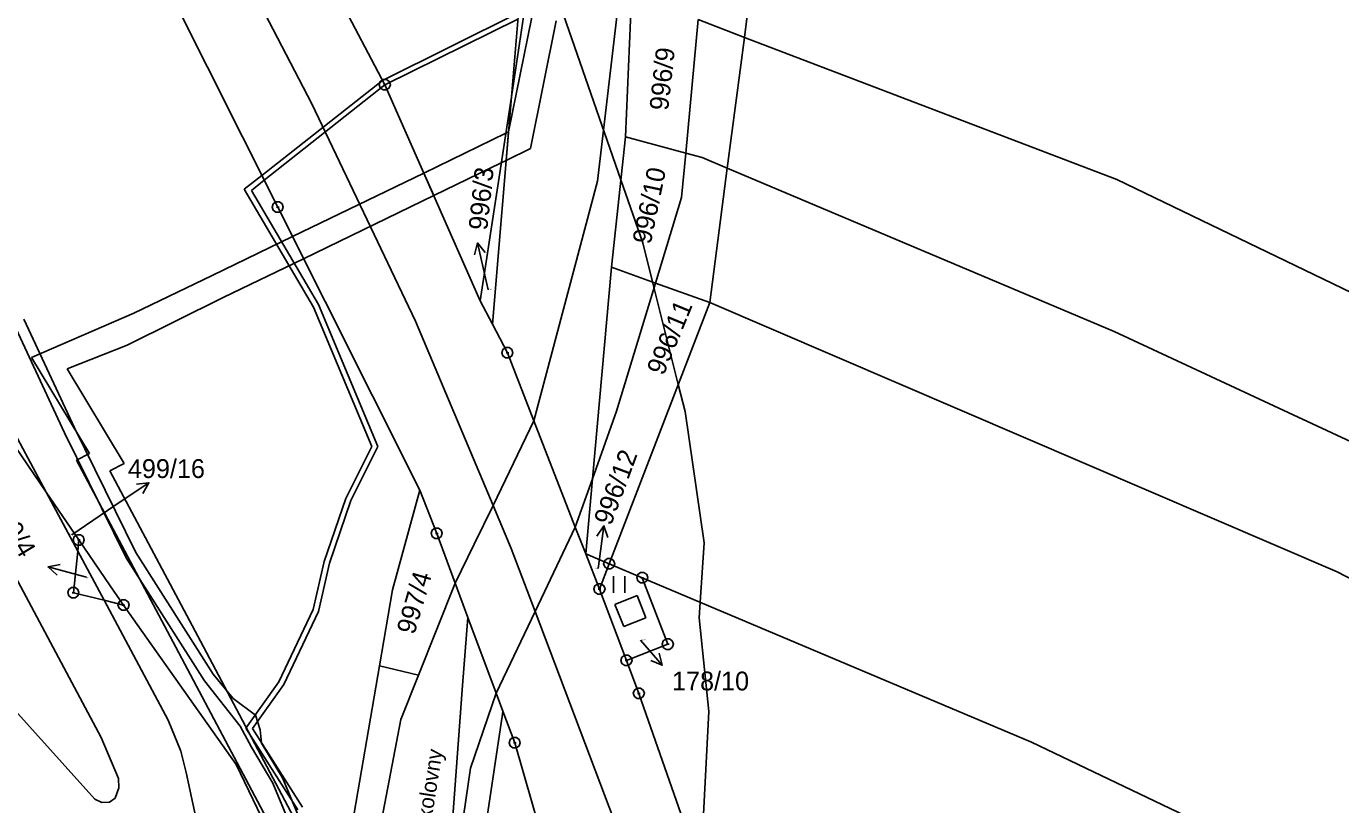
# Model space of a CAD drawing. Extents: x -755359 to -754474, y -1162585 to -1161655.
# Drawn here: x -755164.4 to -755045.7, y -1162431.7 to -1162361.4 of the extents above; entities that cross this region are included whole.
import ezdxf

# ---------------------------------------------------------------- set-up
doc = ezdxf.new("R2010")
doc.units = 0
for name, color, linetype in [('Vrstva 1', 7, 'Continuous'), ('Vrstva 11', 7, 'Continuous'), ('Vrstva 13', 7, 'Continuous'), ('Vrstva 2', 7, 'Continuous'), ('Vrstva 3', 7, 'Continuous'), ('Vrstva 4', 7, 'Continuous'), ('Vrstva 6', 7, 'Continuous'), ('Vrstva 7', 7, 'Continuous'), ('Vrstva 8', 7, 'Continuous')]:
    doc.layers.add(name, color=color, linetype=linetype)

msp = doc.modelspace()

# ---------------------------------------------------------------- linework, layer by layer
at = {"layer": 'Vrstva 1'}
for p, q in [((-755143.37, -1162345.14), (-755132.01, -1162366.71)), ((-755120.58, -1162367.79), (-755117.64, -1162348.46)), ((-755099.55, -1162362.44), (-755098.12, -1162351.47)), ((-755141.68, -1162377.77), (-755154.66, -1162351.82)), ((-755162.59, -1162403.5), (-755194.7, -1162356.4)), ((-755119.82, -1162358.61), (-755120.58, -1162367.79)), ((-755109.73, -1162358.47), (-755110.28, -1162371.41)), ((-755103.73, -1162360.81), (-755099.55, -1162362.44)), ((-755101.09, -1162374.25), (-755099.55, -1162362.44)), ((-755099.55, -1162362.44), (-755065.93, -1162375.26)), ((-755132.01, -1162366.71), (-755123.39, -1162386.22)), ((-755123.39, -1162386.22), (-755120.58, -1162367.79)), ((-755120.58, -1162367.79), (-755122.29, -1162388.33)), ((-755111.53, -1162383.2), (-755110.28, -1162371.41)), ((-755110.28, -1162371.41), (-755104.84, -1162372.89)), ((-755104.84, -1162372.89), (-755103.37, -1162373.29)), ((-755103.37, -1162373.29), (-755101.09, -1162374.25)), ((-755102.66, -1162386.37), (-755101.09, -1162374.25)), ((-755101.09, -1162374.25), (-755066.17, -1162388.99)), ((-755065.93, -1162375.26), (-755012.09, -1162401.26)), ((-755128.84, -1162403.34), (-755141.68, -1162377.77)), ((-755111.53, -1162383.2), (-755113.26, -1162402.31)), ((-755107.56, -1162384.62), (-755111.53, -1162383.2)), ((-755102.66, -1162386.37), (-755107.56, -1162384.62)), ((-755178.91, -1162385.78), (-755157.62, -1162425.68)), ((-755122.29, -1162388.33), (-755123.39, -1162386.22)), ((-755111.75, -1162409.98), (-755102.66, -1162386.37)), ((-755046.04, -1162410.7), (-755102.66, -1162386.37)), ((-755120.94, -1162390.93), (-755122.29, -1162388.33)), ((-755066.17, -1162388.99), (-755029.41, -1162406.11)), ((-755118.55, -1162397.08), (-755120.94, -1162390.93)), ((-755158.19, -1162431.25), (-755190.23, -1162395.62)), ((-755114.81, -1162406.67), (-755118.55, -1162397.08)), ((-755113.26, -1162402.31), (-755113.87, -1162409.08)), ((-755162.59, -1162403.5), (-755159.74, -1162408.83)), ((-755159.64, -1162407.83), (-755162.59, -1162403.5)), ((-755131.31, -1162412.32), (-755128.84, -1162403.34)), ((-755127.32, -1162407.23), (-755128.84, -1162403.34)), ((-755125.65, -1162411.73), (-755127.32, -1162407.23)), ((-755113.87, -1162409.08), (-755114.81, -1162406.67)), ((-755159.64, -1162407.83), (-755159.74, -1162408.83)), ((-755159.64, -1162407.83), (-755156.82, -1162411.96)), ((-755159.74, -1162408.83), (-755160.13, -1162412.59)), ((-755113.87, -1162409.08), (-755111.75, -1162409.98)), ((-755112.63, -1162412.26), (-755113.87, -1162409.08)), ((-755112.63, -1162412.26), (-755111.75, -1162409.98)), ((-755111.75, -1162409.98), (-755108.76, -1162411.24)), ((-754989.82, -1162440.1), (-755046.04, -1162410.7)), ((-755155.59, -1162413.71), (-755156.82, -1162411.96)), ((-755125.65, -1162411.73), (-755128.96, -1162420.05)), ((-755124.5, -1162414.82), (-755125.65, -1162411.73)), ((-755108.76, -1162411.24), (-755073.63, -1162426.1)), ((-755106.46, -1162417.25), (-755108.76, -1162411.24)), ((-755160.13, -1162412.59), (-755157.36, -1162413.27)), ((-755157.36, -1162413.27), (-755151.56, -1162424.12)), ((-755157.36, -1162413.27), (-755155.59, -1162413.71)), ((-755132.49, -1162419.21), (-755131.31, -1162412.32)), ((-755112.63, -1162412.26), (-755110.19, -1162418.72)), ((-755145.43, -1162428.12), (-755155.59, -1162413.71)), ((-755124.5, -1162414.82), (-755125.01, -1162420.99)), ((-755121.95, -1162421.66), (-755124.5, -1162414.82)), ((-755110.19, -1162418.72), (-755106.46, -1162417.25)), ((-755137.03, -1162445.6), (-755132.49, -1162419.21)), ((-755128.96, -1162420.05), (-755132.49, -1162419.21)), ((-755110.19, -1162418.72), (-755109.07, -1162421.69)), ((-755125.01, -1162420.99), (-755126.31, -1162438.59)), ((-755121.35, -1162423.28), (-755121.95, -1162421.66)), ((-755102.04, -1162441.81), (-755109.07, -1162421.69)), ((-755121.39, -1162423.55), (-755122.9, -1162433.61)), ((-755121.35, -1162423.28), (-755121.39, -1162423.55)), ((-755120.28, -1162426.16), (-755121.35, -1162423.28)), ((-755151.56, -1162424.12), (-755150.43, -1162426.9)), ((-755157.62, -1162425.68), (-755156.05, -1162429.38)), ((-755117.59, -1162435.42), (-755120.28, -1162426.16)), ((-755047.73, -1162438.47), (-755073.63, -1162426.1)), ((-755150.43, -1162426.9), (-755149.93, -1162428.84)), ((-755149.93, -1162428.84), (-755146.21, -1162446.45)), ((-755137.03, -1162445.6), (-755145.43, -1162428.12)), ((-755156.05, -1162429.38), (-755156.03, -1162430.21)), ((-755156.34, -1162431.15), (-755156.88, -1162431.52)), ((-755156.03, -1162430.21), (-755156.34, -1162431.15)), ((-755157.56, -1162431.53), (-755158.19, -1162431.25)), ((-755156.88, -1162431.52), (-755157.56, -1162431.53))]:
    msp.add_line(p, q, dxfattribs=at)
at = {"layer": 'Vrstva 11'}
for p, q in [((-755116.36, -1162358.98), (-755110.69, -1162375.3)), ((-755110.69, -1162375.3), (-755108.72, -1162380.99)), ((-755108.72, -1162380.99), (-755107.83, -1162384.52)), ((-755107.83, -1162384.52), (-755105.51, -1162393.77)), ((-755105.51, -1162393.77), (-755104.89, -1162396.23)), ((-755104.89, -1162396.23), (-755103.19, -1162408.08)), ((-755103.19, -1162408.08), (-755103.53, -1162413.45)), ((-755103.53, -1162413.45), (-755103.62, -1162414.85)), ((-755103.62, -1162414.85), (-755102.77, -1162423.32)), ((-755102.77, -1162423.32), (-755103.29, -1162433.76))]:
    msp.add_line(p, q, dxfattribs=at)
at = {"layer": 'Vrstva 13'}
for p, q in [((-755132.22, -1162366.32), (-755119.95, -1162360.2)), ((-755120, -1162360.79), (-755132.01, -1162366.71)), ((-755120.84, -1162370.97), (-755118.74, -1162360.6)), ((-755116.54, -1162360.94), (-755118.85, -1162372.47)), ((-755143.12, -1162374.89), (-755132.22, -1162366.32)), ((-755132.01, -1162366.71), (-755142.9, -1162375.34)), ((-755132.01, -1162366.71), (-755132.22, -1162366.32)), ((-755132.22, -1162366.32), (-755132.01, -1162366.71)), ((-755128.49, -1162374.68), (-755121.08, -1162371.08)), ((-755121.08, -1162371.08), (-755120.84, -1162370.97)), ((-755120.84, -1162370.97), (-755121.06, -1162373.54)), ((-755121.06, -1162373.54), (-755120.84, -1162370.97)), ((-755118.85, -1162372.47), (-755121.06, -1162373.54)), ((-755121.49, -1162373.75), (-755127.59, -1162376.71)), ((-755121.06, -1162373.54), (-755121.49, -1162373.75)), ((-755144.72, -1162376.14), (-755143.12, -1162374.89)), ((-755142.9, -1162375.34), (-755144.06, -1162376.26)), ((-755140.35, -1162380.43), (-755128.49, -1162374.68)), ((-755127.59, -1162376.71), (-755128.49, -1162374.68)), ((-755128.49, -1162374.68), (-755127.59, -1162376.71)), ((-755138.45, -1162386.79), (-755144.72, -1162376.14)), ((-755144.06, -1162376.26), (-755138.01, -1162386.57)), ((-755127.59, -1162376.71), (-755139.35, -1162382.42)), ((-755147.59, -1162383.94), (-755140.35, -1162380.43)), ((-755139.35, -1162382.42), (-755146.61, -1162385.94)), ((-755154.66, -1162387.34), (-755147.59, -1162383.94)), ((-755146.61, -1162385.94), (-755155.26, -1162390.24)), ((-755133.18, -1162399.38), (-755138.45, -1162386.79)), ((-755138.01, -1162386.57), (-755132.64, -1162399.4)), ((-755160.94, -1162398.14), (-755165.49, -1162388.31)), ((-755164.59, -1162387.87), (-755160.04, -1162397.7)), ((-755163.92, -1162391.36), (-755154.66, -1162387.34)), ((-755155.26, -1162390.24), (-755160.7, -1162392.38)), ((-755158.67, -1162400.02), (-755163.92, -1162391.36)), ((-755160.7, -1162392.38), (-755155.53, -1162400.92)), ((-755160.04, -1162397.7), (-755154.48, -1162408.95)), ((-755155.36, -1162409.43), (-755160.94, -1162398.14)), ((-755159.85, -1162400.62), (-755158.67, -1162400.02)), ((-755135.53, -1162404.08), (-755133.18, -1162399.38)), ((-755132.64, -1162399.4), (-755135.07, -1162404.27)), ((-755150.61, -1162418.01), (-755159.85, -1162400.62)), ((-755155.53, -1162400.92), (-755156.83, -1162401.58)), ((-755156.83, -1162401.58), (-755148.65, -1162416.97)), ((-755137.48, -1162409.78), (-755135.53, -1162404.08)), ((-755135.07, -1162404.27), (-755137, -1162409.92)), ((-755148.3, -1162420.56), (-755155.36, -1162409.43)), ((-755154.48, -1162408.95), (-755147.5, -1162419.96)), ((-755138.48, -1162414.11), (-755137.48, -1162409.78)), ((-755137, -1162409.92), (-755138.01, -1162414.28)), ((-755141.58, -1162420.63), (-755138.48, -1162414.11)), ((-755138.01, -1162414.28), (-755141.14, -1162420.89)), ((-755148.65, -1162416.97), (-755139.33, -1162434.57)), ((-755141.31, -1162435.57), (-755150.61, -1162418.01)), ((-755147.5, -1162419.96), (-755145.69, -1162422.16)), ((-755145.06, -1162424.65), (-755148.3, -1162420.56)), ((-755144.55, -1162424.83), (-755141.58, -1162420.63)), ((-755141.14, -1162420.89), (-755143.95, -1162424.85)), ((-755145.69, -1162422.16), (-755143.68, -1162423.65)), ((-755143.68, -1162423.65), (-755143.27, -1162424.99)), ((-755144.06, -1162426.56), (-755145.06, -1162424.65)), ((-755139.87, -1162432.2), (-755144.55, -1162424.83)), ((-755143.95, -1162424.85), (-755139.43, -1162431.96)), ((-755143.27, -1162424.99), (-755143.13, -1162426.18)), ((-755143.13, -1162426.18), (-755141.25, -1162429.33)), ((-755142.13, -1162429.79), (-755144.06, -1162426.56)), ((-755138.6, -1162438.25), (-755142.13, -1162429.79)), ((-755141.25, -1162429.33), (-755137.68, -1162437.85))]:
    msp.add_line(p, q, dxfattribs=at)
at = {"layer": 'Vrstva 3'}
for p, q in [((-755111.35, -1162411.1), (-755111.35, -1162412.6)), ((-755110.35, -1162412.6), (-755110.35, -1162411.1))]:
    msp.add_line(p, q, dxfattribs=at)
at = {"layer": 'Vrstva 4'}
for p, q in [((-755112.82, -1162375.43), (-755109.24, -1162345.2)), ((-755103.73, -1162360.81), (-755104.84, -1162372.89)), ((-755182.37, -1162366.53), (-755162.59, -1162403.5)), ((-755104.84, -1162372.89), (-755105.21, -1162376.88)), ((-755118.55, -1162397.08), (-755112.82, -1162375.43)), ((-755105.21, -1162376.88), (-755107.56, -1162384.62)), ((-755107.56, -1162384.62), (-755111.08, -1162396.2)), ((-755111.08, -1162396.2), (-755113.26, -1162402.31)), ((-755118.55, -1162397.08), (-755122.24, -1162404.71)), ((-755113.26, -1162402.31), (-755114.81, -1162406.67)), ((-755122.24, -1162404.71), (-755123.95, -1162408.22)), ((-755118.44, -1162414.3), (-755114.81, -1162406.67)), ((-755123.95, -1162408.22), (-755125.65, -1162411.73)), ((-755159.74, -1162408.83), (-755157.36, -1162413.27)), ((-755109.24, -1162412.85), (-755111.25, -1162413.65)), ((-755108.45, -1162414.86), (-755109.24, -1162412.85)), ((-755121.95, -1162421.66), (-755118.44, -1162414.3)), ((-755111.25, -1162413.65), (-755110.44, -1162415.65)), ((-755110.44, -1162415.65), (-755108.45, -1162414.86)), ((-755128.96, -1162420.05), (-755130.55, -1162424.05)), ((-755124.28, -1162428.44), (-755121.95, -1162421.66)), ((-755130.55, -1162424.05), (-755134.62, -1162445.29)), ((-755126.85, -1162446.31), (-755124.28, -1162428.44))]:
    msp.add_line(p, q, dxfattribs=at)
at = {"layer": 'Vrstva 6'}
for p, q in [((-755148.58, -1162349.19), (-755138.6, -1162368.43)), ((-755138.6, -1162368.43), (-755129.24, -1162388.07)), ((-755129.24, -1162388.07), (-755122.24, -1162404.71)), ((-755122.24, -1162404.71), (-755120.61, -1162408.59)), ((-755118.44, -1162414.3), (-755120.61, -1162408.59)), ((-755110.65, -1162434.84), (-755118.44, -1162414.3))]:
    msp.add_line(p, q, dxfattribs=at)
at = {"layer": 'Vrstva 7'}
for p, q in [((-755123.655, -1162380.997), (-755122.98, -1162383.92)), ((-755122.69, -1162385.22), (-755122.98, -1162383.92)), ((-755153.312, -1162402.654), (-755155.8, -1162404.33)), ((-755160.28, -1162407.35), (-755155.8, -1162404.33)), ((-755112.229, -1162406.547), (-755112.63, -1162409.52)), ((-755112.75, -1162410.42), (-755112.63, -1162409.52)), ((-755162.418, -1162410.264), (-755159.52, -1162411.04)), ((-755158.95, -1162411.19), (-755159.52, -1162411.04)), ((-755106.965, -1162419.149), (-755108.94, -1162416.89))]:
    msp.add_line(p, q, dxfattribs=at)
for points in [[(-755123.917, -1162382.084), (-755123.655, -1162380.997), (-755122.943, -1162381.859)], [(-755154.42, -1162402.798), (-755153.312, -1162402.654), (-755153.862, -1162403.628)], [(-755112.858, -1162407.471), (-755112.229, -1162406.547), (-755111.867, -1162407.605)], [(-755161.581, -1162411.005), (-755162.418, -1162410.264), (-755161.322, -1162410.039)], [(-755107.247, -1162418.067), (-755106.965, -1162419.149), (-755108, -1162418.725)]]:
    msp.add_lwpolyline(points, dxfattribs=at)
at = {"layer": 'Vrstva 8'}
for p, q in [((-755132.13, -1162366.71), (-755131.89, -1162366.71)), ((-755141.8, -1162377.77), (-755141.56, -1162377.77)), ((-755121.06, -1162390.93), (-755120.82, -1162390.93)), ((-755127.44, -1162407.23), (-755127.2, -1162407.23)), ((-755159.76, -1162407.83), (-755159.52, -1162407.83)), ((-755111.87, -1162409.98), (-755111.63, -1162409.98)), ((-755108.88, -1162411.24), (-755108.64, -1162411.24)), ((-755160.25, -1162412.59), (-755160.01, -1162412.59)), ((-755112.75, -1162412.26), (-755112.51, -1162412.26)), ((-755155.71, -1162413.71), (-755155.47, -1162413.71)), ((-755106.58, -1162417.25), (-755106.34, -1162417.25)), ((-755110.31, -1162418.72), (-755110.07, -1162418.72)), ((-755109.19, -1162421.69), (-755108.95, -1162421.69)), ((-755120.4, -1162426.16), (-755120.16, -1162426.16))]:
    msp.add_line(p, q, dxfattribs=at)
for points in [[(-755131.86, -1162366.23), (-755131.61, -1162366.41), (-755131.51, -1162366.7), (-755131.61, -1162366.99), (-755131.86, -1162367.17), (-755132.17, -1162367.17), (-755132.42, -1162366.99), (-755132.52, -1162366.7), (-755132.42, -1162366.41), (-755132.17, -1162366.23)], [(-755141.53, -1162377.29), (-755141.28, -1162377.47), (-755141.18, -1162377.76), (-755141.28, -1162378.05), (-755141.53, -1162378.23), (-755141.84, -1162378.23), (-755142.09, -1162378.05), (-755142.19, -1162377.76), (-755142.09, -1162377.47), (-755141.84, -1162377.29)], [(-755120.79, -1162390.45), (-755120.54, -1162390.63), (-755120.44, -1162390.92), (-755120.54, -1162391.21), (-755120.79, -1162391.39), (-755121.1, -1162391.39), (-755121.35, -1162391.21), (-755121.45, -1162390.92), (-755121.35, -1162390.63), (-755121.1, -1162390.45)], [(-755159.49, -1162407.35), (-755159.24, -1162407.53), (-755159.14, -1162407.82), (-755159.24, -1162408.11), (-755159.49, -1162408.29), (-755159.8, -1162408.29), (-755160.05, -1162408.11), (-755160.15, -1162407.82), (-755160.05, -1162407.53), (-755159.8, -1162407.35)], [(-755127.17, -1162406.75), (-755126.92, -1162406.93), (-755126.82, -1162407.22), (-755126.92, -1162407.51), (-755127.17, -1162407.69), (-755127.48, -1162407.69), (-755127.73, -1162407.51), (-755127.83, -1162407.22), (-755127.73, -1162406.93), (-755127.48, -1162406.75)], [(-755111.6, -1162409.5), (-755111.35, -1162409.68), (-755111.25, -1162409.97), (-755111.35, -1162410.26), (-755111.6, -1162410.44), (-755111.91, -1162410.44), (-755112.16, -1162410.26), (-755112.26, -1162409.97), (-755112.16, -1162409.68), (-755111.91, -1162409.5)], [(-755108.61, -1162410.76), (-755108.36, -1162410.94), (-755108.26, -1162411.23), (-755108.36, -1162411.52), (-755108.61, -1162411.7), (-755108.92, -1162411.7), (-755109.17, -1162411.52), (-755109.27, -1162411.23), (-755109.17, -1162410.94), (-755108.92, -1162410.76)], [(-755159.98, -1162412.11), (-755159.73, -1162412.29), (-755159.63, -1162412.58), (-755159.73, -1162412.87), (-755159.98, -1162413.05), (-755160.29, -1162413.05), (-755160.54, -1162412.87), (-755160.64, -1162412.58), (-755160.54, -1162412.29), (-755160.29, -1162412.11)], [(-755112.48, -1162411.78), (-755112.23, -1162411.96), (-755112.13, -1162412.25), (-755112.23, -1162412.54), (-755112.48, -1162412.72), (-755112.79, -1162412.72), (-755113.04, -1162412.54), (-755113.14, -1162412.25), (-755113.04, -1162411.96), (-755112.79, -1162411.78)], [(-755155.44, -1162413.23), (-755155.19, -1162413.41), (-755155.09, -1162413.7), (-755155.19, -1162413.99), (-755155.44, -1162414.17), (-755155.75, -1162414.17), (-755156, -1162413.99), (-755156.1, -1162413.7), (-755156, -1162413.41), (-755155.75, -1162413.23)], [(-755106.31, -1162416.77), (-755106.06, -1162416.95), (-755105.96, -1162417.24), (-755106.06, -1162417.53), (-755106.31, -1162417.71), (-755106.62, -1162417.71), (-755106.87, -1162417.53), (-755106.97, -1162417.24), (-755106.87, -1162416.95), (-755106.62, -1162416.77)], [(-755110.04, -1162418.24), (-755109.79, -1162418.42), (-755109.69, -1162418.71), (-755109.79, -1162419), (-755110.04, -1162419.18), (-755110.35, -1162419.18), (-755110.6, -1162419), (-755110.7, -1162418.71), (-755110.6, -1162418.42), (-755110.35, -1162418.24)], [(-755108.92, -1162421.21), (-755108.67, -1162421.39), (-755108.57, -1162421.68), (-755108.67, -1162421.97), (-755108.92, -1162422.15), (-755109.23, -1162422.15), (-755109.48, -1162421.97), (-755109.58, -1162421.68), (-755109.48, -1162421.39), (-755109.23, -1162421.21)], [(-755120.13, -1162425.68), (-755119.88, -1162425.86), (-755119.78, -1162426.15), (-755119.88, -1162426.44), (-755120.13, -1162426.62), (-755120.44, -1162426.62), (-755120.69, -1162426.44), (-755120.79, -1162426.15), (-755120.69, -1162425.86), (-755120.44, -1162425.68)]]:
    msp.add_lwpolyline(points, close=True, dxfattribs=at)

# ---------------------------------------------------------------- texts
at = {"layer": 'Vrstva 2'}
for s, rotation, p in [('996/9', 83.70913, (-755106.434, -1162369.094)), ('996/10', 78.32333, (-755108.012, -1162381.188)), ('996/11', 67.49443, (-755106.849, -1162393.051)), ('997/4', 73.79696, (-755129.344, -1162416.452))]:
    msp.add_text(s, height=1.7, rotation=rotation, dxfattribs=at).set_placement(p)
for s, p in [('996/3', (-755122.676, -1162385.22)), ('499/16', (-755160.502, -1162407.35)), ('996/12', (-755112.976, -1162410.42)), ('499/4', (-755159.066, -1162411.29)), ('178/10', (-755108.917, -1162416.89))]:
    msp.add_text(s, height=0.1, dxfattribs=at).set_placement(p)
at = {"layer": 'Vrstva 7'}
for s, height, rotation, p in [('996/3', 1.7, 83.99561, (-755122.765, -1162379.904)), ('996/12', 1.7, 69.61437, (-755111.59, -1162406.607)), ('499/4', 1.7, 300.97473, (-755167.806, -1162404.679)), ('U Sokolovny', 1.4, 81.01623, (-755128.424, -1162437.217))]:
    msp.add_text(s, height=height, rotation=rotation, dxfattribs=at).set_placement(p)
for s, p in [('499/16', (-755155.204, -1162402.23)), ('178/10', (-755106.077, -1162421.42))]:
    msp.add_text(s, height=1.7, dxfattribs=at).set_placement(p)

doc.saveas('drawing.dxf')
